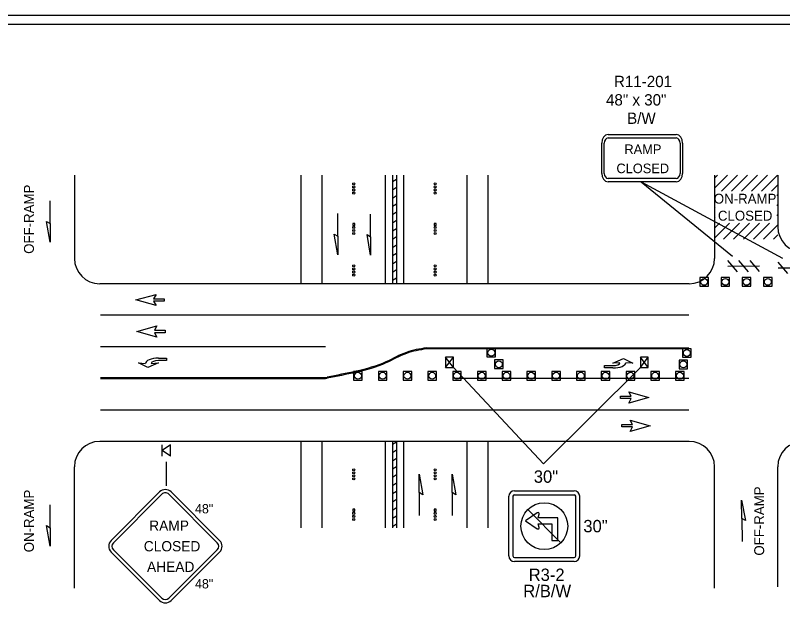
# Model space of a CAD drawing. Extents: x 99988 to 100172, y 99995 to 100047.
# Drawn here: x 100006.52 to 100011.94, y 100006.27 to 100010.44 of the extents above; entities that cross this region are included whole.
import ezdxf

# ---------------------------------------------------------------- set-up
doc = ezdxf.new("R2010")
doc.units = 0
for name, color, linetype in [('Default', 7, 'Continuous'), ('RD_MK_TrafficArrowType1SNew', 7, 'Continuous'), ('RD_MK_TrafficArrowType2LNew', 7, 'Continuous'), ('SH_DE_DetailBody1Text', 7, 'Continuous'), ('SH_GI_PlotLimits', 7, 'Continuous'), ('SH_GI_SheetBorder', 7, 'Continuous'), ('SH_GI_TrafficMvmntArrowRt1Lane', 7, 'Continuous'), ('TR_SN_RegulatorySigns', 7, 'Continuous'), ('TR_SN_WarningSigns', 7, 'Continuous'), ('TR_WZ_BarricadeType3', 7, 'Continuous'), ('TR_WZ_TrafficSafetyCone', 7, 'Continuous'), ('TR_WZ_WorkZoneDetails', 7, 'Continuous')]:
    doc.layers.add(name, color=color, linetype=linetype)

msp = doc.modelspace()

# ---------------------------------------------------------------- linework, layer by layer
at = {"layer": 'Default'}
for p, q in [((100009.5612, 100007.9496), (100009.6156, 100008.0221)), ((100009.6156, 100007.9496), (100009.5612, 100008.0221)), ((100010.9374, 100007.9496), (100010.9917, 100008.0221)), ((100010.9917, 100007.9496), (100010.9374, 100008.0221)), ((100009.5883, 100007.9857), (100009.5883, 100007.9857)), ((100009.5884, 100007.9858), (100009.5884, 100007.9858)), ((100010.9645, 100007.9858), (100010.9645, 100007.9858)), ((100010.9645, 100007.9857), (100010.9645, 100007.9857)), ((100007.6173, 100007.4044), (100007.5595, 100007.3641)), ((100007.5595, 100007.324), (100007.5595, 100007.4044)), ((100007.6173, 100007.324), (100007.6173, 100007.4044)), ((100007.6173, 100007.324), (100007.5595, 100007.3641))]:
    msp.add_line(p, q, dxfattribs=at)
for points in [[(100009.5612, 100007.9496), (100009.6156, 100007.9496), (100009.6156, 100008.0221), (100009.5612, 100008.0221)], [(100010.9374, 100007.9496), (100010.9917, 100007.9496), (100010.9917, 100008.0221), (100010.9374, 100008.0221)]]:
    msp.add_lwpolyline(points, close=True, dxfattribs=at)
at = {"layer": 'RD_MK_TrafficArrowType1SNew'}
for points in [[(100007.5731, 100008.4189), (100007.4981, 100008.4189), (100007.5148, 100008.3876), (100007.3731, 100008.4272), (100007.5148, 100008.4668), (100007.4981, 100008.4355), (100007.5731, 100008.4355)], [(100007.5784, 100008.1959), (100007.5034, 100008.1959), (100007.5201, 100008.1646), (100007.3784, 100008.2042), (100007.5201, 100008.2438), (100007.5034, 100008.2126), (100007.5784, 100008.2126)], [(100010.7971, 100007.7469), (100010.8721, 100007.7469), (100010.8554, 100007.7782), (100010.9971, 100007.7386), (100010.8554, 100007.699), (100010.8721, 100007.7303), (100010.7971, 100007.7303)], [(100010.8058, 100007.5464), (100010.8808, 100007.5464), (100010.8641, 100007.5777), (100011.0058, 100007.5381), (100010.8641, 100007.4985), (100010.8808, 100007.5298), (100010.8058, 100007.5298)]]:
    msp.add_lwpolyline(points, close=True, dxfattribs=at)
at = {"layer": 'RD_MK_TrafficArrowType2LNew'}
for p, q in [((100007.4401, 100007.9785), (100007.4401, 100007.9785)), ((100007.4818, 100007.9785), (100007.4818, 100007.9785)), ((100007.5318, 100008.016), (100007.5318, 100008.016)), ((100007.5318, 100008.016), (100007.5318, 100008.016)), ((100007.5318, 100007.9993), (100007.5318, 100007.9993)), ((100010.7926, 100007.9841), (100010.7926, 100007.9841)), ((100010.8343, 100007.9841), (100010.8343, 100007.9841)), ((100010.7426, 100007.9633), (100010.7426, 100007.9633)), ((100010.7426, 100007.9467), (100010.7426, 100007.9467)), ((100010.7426, 100007.9467), (100010.7426, 100007.9467))]:
    msp.add_line(p, q, dxfattribs=at)
for points in [[(100007.4818, 100007.9785), (100007.5318, 100007.9827), (100007.4568, 100007.9493), (100007.3901, 100007.9827), (100007.4401, 100007.9785)], [(100007.5318, 100008.016), (100007.5901, 100008.016), (100007.5901, 100007.9993), (100007.5318, 100007.9993)], [(100010.7926, 100007.9841), (100010.7426, 100007.98), (100010.8176, 100008.0133), (100010.8843, 100007.98), (100010.8343, 100007.9841)], [(100010.7426, 100007.9467), (100010.6843, 100007.9467), (100010.6843, 100007.9633), (100010.7426, 100007.9633)]]:
    msp.add_lwpolyline(points, dxfattribs=at)
for centre, major_axis, ratio, start_param in [((100007.5318, 100007.9785), (-0.0917, 0), 0.40879, 4.712524), ((100007.5318, 100007.9785), (-0.05, 0), 0.41611, 4.712518), ((100010.7426, 100007.9841), (0.05, 0), 0.41611, 4.712518), ((100010.7426, 100007.9841), (0.0917, 0), 0.40879, 4.712524)]:
    msp.add_ellipse(centre, major_axis=major_axis, ratio=ratio, start_param=start_param, end_param=6.283185, dxfattribs=at)
at = {"layer": 'SH_GI_PlotLimits'}
msp.add_lwpolyline([(99999.3125, 99999.9375), (100015.8125, 99999.9375), (100015.8125, 100010.4375), (99999.3125, 100010.4375)], close=True, dxfattribs=at)
at = {"layer": 'SH_GI_SheetBorder'}
msp.add_line((100000, 100010.375), (100015.75, 100010.375), dxfattribs=at)
at = {"layer": 'SH_GI_TrafficMvmntArrowRt1Lane'}
for p, q in [((100006.7678, 100008.9661), (100006.7678, 100009.1268)), ((100008.7984, 100008.8766), (100008.7984, 100009.0373)), ((100009.0314, 100008.8735), (100009.0314, 100009.0343)), ((100009.3737, 100007.0664), (100009.3737, 100006.9057)), ((100009.6068, 100007.0664), (100009.6068, 100006.9057)), ((100006.7678, 100006.8186), (100006.7679, 100006.9793)), ((100011.6536, 100006.8828), (100011.6557, 100006.722))]:
    msp.add_line(p, q, dxfattribs=at)
for points in [[(100006.7678, 100008.8351), (100006.742, 100008.981), (100006.7678, 100008.9661)], [(100008.7984, 100008.7456), (100008.7726, 100008.8915), (100008.7984, 100008.8766)], [(100009.0314, 100008.7425), (100009.0057, 100008.8884), (100009.0314, 100008.8735)], [(100009.3737, 100007.1975), (100009.3994, 100007.0516), (100009.3737, 100007.0664)], [(100009.6068, 100007.1975), (100009.6325, 100007.0516), (100009.6068, 100007.0664)], [(100011.6518, 100007.0138), (100011.6795, 100006.8683), (100011.6536, 100006.8828)], [(100006.7678, 100006.6875), (100006.7421, 100006.8334), (100006.7678, 100006.8186)]]:
    msp.add_lwpolyline(points, close=True, dxfattribs=at)
at = {"layer": 'TR_SN_RegulatorySigns'}
for p, q in [((100010.0473, 100007.0796), (100010.469, 100007.0796)), ((100010.0473, 100007.0516), (100010.469, 100007.0516)), ((100010.0081, 100006.6187), (100010.0081, 100007.0405)), ((100010.0361, 100007.0405), (100010.0361, 100006.6187)), ((100010.4801, 100006.6187), (100010.4801, 100007.0405)), ((100010.5081, 100007.0405), (100010.5081, 100006.6187)), ((100010.1412, 100006.9465), (100010.3751, 100006.7127)), ((100010.2087, 100006.9243), (100010.1261, 100006.8677)), ((100010.2087, 100006.9243), (100010.2087, 100006.9243)), ((100010.2139, 100006.8893), (100010.2218, 100006.9146)), ((100010.3538, 100006.8892), (100010.2139, 100006.8892)), ((100010.3538, 100006.7288), (100010.3538, 100006.8892)), ((100010.1261, 100006.8677), (100010.2087, 100006.8111)), ((100010.2139, 100006.8462), (100010.3108, 100006.8462)), ((100010.2218, 100006.8208), (100010.2139, 100006.8461)), ((100010.3108, 100006.8462), (100010.3108, 100006.7288)), ((100010.3108, 100006.7288), (100010.3538, 100006.7288)), ((100010.0473, 100006.6076), (100010.469, 100006.6076)), ((100010.469, 100006.5796), (100010.0473, 100006.5796))]:
    msp.add_line(p, q, dxfattribs=at)
for points in [[(100010.7086, 100009.5951), (100011.1908, 100009.5951)], [(100010.7086, 100009.5713), (100011.1908, 100009.5713)], [(100010.6639, 100009.3213), (100010.6639, 100009.5356)], [(100010.6818, 100009.3213), (100010.6818, 100009.5356)], [(100011.2176, 100009.5356), (100011.2176, 100009.3213)], [(100011.2354, 100009.5356), (100011.2354, 100009.3213)], [(100011.1908, 100009.2856), (100010.7086, 100009.2856)], [(100011.1908, 100009.2618), (100010.7086, 100009.2618)]]:
    msp.add_lwpolyline(points, dxfattribs=at)
msp.add_circle((100010.2581, 100006.8296), 0.1654, dxfattribs=at)
for centre, radius, start, end in [((100010.0473, 100007.0405), 0.0392, 90, 180), ((100010.0473, 100007.0405), 0.0111, 90, 180), ((100010.469, 100007.0405), 0.0392, 0, 90), ((100010.469, 100007.0405), 0.0111, 0, 90), ((100010.0473, 100006.6188), 0.0392, 180, 270), ((100010.0473, 100006.6188), 0.0111, 180, 270), ((100010.469, 100006.6188), 0.0111, 270, 0), ((100010.469, 100006.6188), 0.0392, 270, 0)]:
    msp.add_arc(centre, radius, start, end, dxfattribs=at)
for centre, major_axis, ratio, start_param, end_param in [((100010.7086, 100009.5356), (0, -0.0595), 0.75, 3.141593, 4.712389), ((100011.1908, 100009.5356), (0, 0.0595), 0.75, 4.712389, 6.283185), ((100010.7086, 100009.5356), (0, -0.0357), 0.75, 3.141593, 4.712389), ((100011.1908, 100009.5356), (0, 0.0357), 0.75, 4.712389, 6.283185), ((100010.7086, 100009.3213), (0, -0.0595), 0.75, 4.712389, 6.283185), ((100010.7086, 100009.3213), (0, -0.0357), 0.75, 4.712389, 6.283185), ((100011.1908, 100009.3213), (0, 0.0357), 0.75, 3.141593, 4.712389), ((100011.1908, 100009.3213), (0, 0.0595), 0.75, 3.141593, 4.712389), ((100010.2136, 100006.9172), (0.00326, 0.00797), 0.999219, 4.797876, 7.277037), ((100010.2136, 100006.8182), (0.00326, 0.00797), 0.999219, 2.929663, 5.403892)]:
    msp.add_ellipse(centre, major_axis=major_axis, ratio=ratio, start_param=start_param, end_param=end_param, dxfattribs=at)
at = {"layer": 'TR_SN_WarningSigns'}
for p, q in [((100007.1974, 100006.7284), (100007.5401, 100007.0711)), ((100007.2137, 100006.7121), (100007.5564, 100007.0547)), ((100007.6053, 100007.0547), (100007.948, 100006.7121)), ((100007.6216, 100007.0711), (100007.9643, 100006.7284)), ((100007.5401, 100006.3041), (100007.1974, 100006.6468)), ((100007.5564, 100006.3204), (100007.2137, 100006.6631)), ((100007.948, 100006.6631), (100007.6053, 100006.3204)), ((100007.9643, 100006.6468), (100007.6216, 100006.3041))]:
    msp.add_line(p, q, dxfattribs=at)
for centre, radius, start, end in [((100007.5809, 100007.0303), 0.0577, 44.9963, 134.9997), ((100007.5809, 100007.0303), 0.0346, 44.9963, 134.9997), ((100007.2382, 100006.6876), 0.0577, 134.9966, 224.9936), ((100007.9235, 100006.6876), 0.0577, 314.9994, 44.9948), ((100007.2382, 100006.6876), 0.0346, 134.9966, 224.9936), ((100007.9235, 100006.6876), 0.0346, 314.9994, 44.9948), ((100007.5808, 100006.3449), 0.0577, 225, 314.9996), ((100007.5808, 100006.3449), 0.0346, 225, 314.9996)]:
    msp.add_arc(centre, radius, start, end, dxfattribs=at)
at = {"layer": 'TR_WZ_BarricadeType3'}
for p, q in [((100011.6222, 100008.6262), (100011.5547, 100008.7049)), ((100011.7007, 100008.6269), (100011.6332, 100008.7056)), ((100011.7792, 100008.6276), (100011.7117, 100008.7063)), ((100011.9777, 100008.6146), (100011.91, 100008.6932)), ((100011.555, 100008.6653), (100011.7788, 100008.6672)), ((100011.9104, 100008.6535), (100012.1342, 100008.6558))]:
    msp.add_line(p, q, dxfattribs=at)
at = {"layer": 'TR_WZ_TrafficSafetyCone'}
for points in [[(100011.4178, 100008.5246), (100011.4178, 100008.5853), (100011.3571, 100008.5853), (100011.3571, 100008.5246)], [(100011.5678, 100008.5246), (100011.5678, 100008.5853), (100011.5071, 100008.5853), (100011.5071, 100008.5246)], [(100011.7178, 100008.5246), (100011.7178, 100008.5853), (100011.6571, 100008.5853), (100011.6571, 100008.5246)], [(100011.8678, 100008.5246), (100011.8678, 100008.5853), (100011.8071, 100008.5853), (100011.8071, 100008.5246)], [(100009.8529, 100008.0243), (100009.9137, 100008.0243), (100009.9137, 100008.085), (100009.8529, 100008.085)], [(100011.2956, 100008.0223), (100011.2956, 100008.083), (100011.2349, 100008.083), (100011.2349, 100008.0223)], [(100009.9069, 100007.9428), (100009.9677, 100007.9428), (100009.9677, 100008.0035), (100009.9069, 100008.0035)], [(100011.2711, 100007.9418), (100011.2711, 100008.0025), (100011.2105, 100008.0025), (100011.2105, 100007.9418)], [(100008.911, 100007.8613), (100008.9717, 100007.8613), (100008.9717, 100007.922), (100008.911, 100007.922)], [(100009.086, 100007.8613), (100009.1467, 100007.8613), (100009.1467, 100007.922), (100009.086, 100007.922)], [(100009.261, 100007.8613), (100009.3217, 100007.8613), (100009.3217, 100007.922), (100009.261, 100007.922)], [(100009.436, 100007.8613), (100009.4967, 100007.8613), (100009.4967, 100007.922), (100009.436, 100007.922)], [(100009.6717, 100007.8613), (100009.6717, 100007.922), (100009.611, 100007.922), (100009.611, 100007.8613)], [(100009.786, 100007.8613), (100009.8467, 100007.8613), (100009.8467, 100007.922), (100009.786, 100007.922)], [(100009.961, 100007.8613), (100010.0217, 100007.8613), (100010.0217, 100007.922), (100009.961, 100007.922)], [(100010.1967, 100007.8613), (100010.1967, 100007.922), (100010.136, 100007.922), (100010.136, 100007.8613)], [(100010.311, 100007.8613), (100010.3717, 100007.8613), (100010.3717, 100007.922), (100010.311, 100007.922)], [(100010.5467, 100007.8613), (100010.5467, 100007.922), (100010.486, 100007.922), (100010.486, 100007.8613)], [(100010.7217, 100007.8613), (100010.7217, 100007.922), (100010.661, 100007.922), (100010.661, 100007.8613)], [(100010.8967, 100007.8613), (100010.8967, 100007.922), (100010.836, 100007.922), (100010.836, 100007.8613)], [(100011.0717, 100007.8613), (100011.0717, 100007.922), (100011.011, 100007.922), (100011.011, 100007.8613)], [(100011.2467, 100007.8613), (100011.2467, 100007.922), (100011.186, 100007.922), (100011.186, 100007.8613)]]:
    msp.add_lwpolyline(points, close=True, dxfattribs=at)
for centre in [(100011.3875, 100008.5549), (100011.5375, 100008.5549), (100011.6875, 100008.5549), (100011.8375, 100008.5549), (100009.8833, 100008.0547), (100011.2653, 100008.0526), (100009.9373, 100007.9732), (100011.2408, 100007.9721), (100008.9413, 100007.8916), (100009.1163, 100007.8916), (100009.2913, 100007.8916), (100009.4663, 100007.8916), (100009.6413, 100007.8916), (100009.8163, 100007.8916), (100009.9913, 100007.8916), (100010.1663, 100007.8916), (100010.3413, 100007.8916), (100010.5163, 100007.8916), (100010.6913, 100007.8916), (100010.8663, 100007.8916), (100011.0413, 100007.8916), (100011.2163, 100007.8916)]:
    msp.add_circle(centre, 0.0244, dxfattribs=at)
at = {"layer": 'TR_WZ_WorkZoneDetails'}
for p, q in [((100006.9383, 100009.3085), (100006.9383, 100008.7205)), ((100008.5382, 100009.3085), (100008.5382, 100008.5417)), ((100008.6872, 100009.3085), (100008.6872, 100008.5417)), ((100009.135, 100009.3085), (100009.135, 100008.5417)), ((100009.1847, 100009.3085), (100009.1847, 100008.5417)), ((100009.1847, 100009.2631), (100009.2145, 100009.2811)), ((100009.2145, 100009.3085), (100009.2145, 100008.5417)), ((100009.2641, 100009.3085), (100009.2641, 100008.5417)), ((100009.7107, 100009.3085), (100009.7107, 100008.5417)), ((100009.8598, 100009.3085), (100009.8598, 100008.5417)), ((100011.4609, 100009.3085), (100011.4609, 100008.7205)), ((100011.4609, 100009.2878), (100011.4816, 100009.3085)), ((100011.4609, 100009.2171), (100011.5523, 100009.3085)), ((100011.5099, 100009.1954), (100011.623, 100009.3085)), ((100011.5807, 100009.1954), (100011.6937, 100009.3085)), ((100011.6514, 100009.1954), (100011.7644, 100009.3085)), ((100011.7221, 100009.1954), (100011.8352, 100009.3085)), ((100011.7928, 100009.1954), (100011.9059, 100009.3085)), ((100011.9079, 100009.3085), (100011.9079, 100008.944)), ((100009.1847, 100009.205), (100009.2145, 100009.223)), ((100010.9435, 100009.2624), (100011.5885, 100008.7361)), ((100010.9435, 100009.2624), (100011.9417, 100008.7232)), ((100011.8635, 100009.1954), (100011.9079, 100009.2399)), ((100009.1847, 100009.147), (100009.2145, 100009.165)), ((100011.9026, 100009.1638), (100011.9079, 100009.1692)), ((100009.1847, 100009.0889), (100009.2145, 100009.1069)), ((100011.4609, 100009.1464), (100011.466, 100009.1516)), ((100011.4609, 100009.0757), (100011.466, 100009.0808)), ((100011.9026, 100009.0931), (100011.9079, 100009.0984)), ((100009.1847, 100009.0308), (100009.2145, 100009.0489)), ((100011.4609, 100009.005), (100011.466, 100009.0101)), ((100011.9026, 100009.0224), (100011.9079, 100009.0277)), ((100009.1847, 100008.9728), (100009.2145, 100008.9908)), ((100011.4609, 100008.9342), (100011.4958, 100008.9692)), ((100011.4609, 100008.8635), (100011.5665, 100008.9692)), ((100011.5242, 100008.8561), (100011.6372, 100008.9692)), ((100011.5949, 100008.8561), (100011.708, 100008.9692)), ((100011.6656, 100008.8561), (100011.7787, 100008.9692)), ((100011.7363, 100008.8561), (100011.8494, 100008.9692)), ((100011.807, 100008.8561), (100011.9079, 100008.957)), ((100009.1847, 100008.9147), (100009.2145, 100008.9327)), ((100009.1847, 100008.8567), (100009.2145, 100008.8747)), ((100011.8777, 100008.8561), (100011.9079, 100008.8863)), ((100009.1847, 100008.7986), (100009.2145, 100008.8166)), ((100009.1847, 100008.7406), (100009.2145, 100008.7586)), ((100009.1847, 100008.6825), (100009.2145, 100008.7005)), ((100009.1847, 100008.6244), (100009.2145, 100008.6424)), ((100009.1847, 100008.5664), (100009.2145, 100008.5844)), ((100011.2821, 100008.5417), (100007.117, 100008.5417)), ((100011.2794, 100008.32), (100007.123, 100008.32)), ((100008.7125, 100008.0965), (100007.123, 100008.0965)), ((100009.4259, 100008.089), (100011.2787, 100008.089)), ((100011.2787, 100008.0815), (100009.426, 100008.0815)), ((100009.6156, 100007.9496), (100010.2536, 100007.2701)), ((100010.9374, 100007.9496), (100010.2536, 100007.2701)), ((100007.123, 100007.8804), (100008.7115, 100007.8804)), ((100007.123, 100007.8729), (100008.7125, 100007.8729)), ((100007.4179, 100007.872), (100007.418, 100007.8721)), ((100007.8318, 100007.8804), (100007.8764, 100007.8804)), ((100008.7115, 100007.8804), (100008.7235, 100007.8823)), ((100008.7125, 100007.8729), (100008.7236, 100007.8749)), ((100011.2787, 100007.8729), (100009.6229, 100007.8729)), ((100011.2787, 100007.6494), (100007.123, 100007.6494)), ((100011.2821, 100007.4277), (100007.117, 100007.4277)), ((100008.5382, 100007.4277), (100008.5382, 100006.8187)), ((100008.6872, 100007.4277), (100008.6872, 100006.8187)), ((100009.135, 100007.4277), (100009.135, 100006.8187)), ((100009.1847, 100007.4277), (100009.1847, 100006.8187)), ((100009.2145, 100007.4277), (100009.2145, 100006.8187)), ((100009.2641, 100007.4277), (100009.2641, 100006.8187)), ((100009.7107, 100007.4277), (100009.7107, 100006.8187)), ((100009.8598, 100007.4277), (100009.8598, 100006.8187)), ((100009.1847, 100007.4074), (100009.2145, 100007.4255)), ((100009.1847, 100007.3494), (100009.2145, 100007.3674)), ((100007.5869, 100007.284), (100007.5869, 100007.114)), ((100009.1847, 100007.2913), (100009.2145, 100007.3094)), ((100006.9383, 100006.3918), (100006.9383, 100007.2489)), ((100009.1847, 100007.2333), (100009.2145, 100007.2513)), ((100011.4609, 100006.3918), (100011.4609, 100007.2489)), ((100011.9079, 100006.4019), (100011.9079, 100007.2489)), ((100009.1847, 100007.1752), (100009.2145, 100007.1933)), ((100009.1847, 100007.1172), (100009.2145, 100007.1352)), ((100009.1847, 100007.0591), (100009.2145, 100007.0771)), ((100009.1847, 100007.001), (100009.2145, 100007.019)), ((100009.1847, 100006.943), (100009.2145, 100006.961)), ((100009.1847, 100006.8849), (100009.2145, 100006.9029)), ((100009.1847, 100006.8269), (100009.2145, 100006.8449))]:
    msp.add_line(p, q, dxfattribs=at)
for points in [[(100008.9185, 100008.9537), (100008.9185, 100008.9677), (100008.9044, 100008.9677), (100008.9044, 100008.9537), (100008.9185, 100008.9537)], [(100009.4947, 100008.9537), (100009.4947, 100008.9677), (100009.4806, 100008.9677), (100009.4806, 100008.9537), (100009.4947, 100008.9537)], [(100008.9185, 100006.9344), (100008.9185, 100006.9485), (100008.9044, 100006.9485), (100008.9044, 100006.9344), (100008.9185, 100006.9344)], [(100009.4947, 100006.9344), (100009.4947, 100006.9485), (100009.4806, 100006.9485), (100009.4806, 100006.9344), (100009.4947, 100006.9344)]]:
    msp.add_lwpolyline(points, dxfattribs=at)
for centre in [(100008.9115, 100009.2468), (100008.9115, 100009.2253), (100009.4877, 100009.2468), (100009.4877, 100009.2253), (100008.9115, 100009.2039), (100008.9115, 100009.1824), (100009.4877, 100009.2039), (100009.4877, 100009.1824), (100008.9115, 100008.9393), (100009.4877, 100008.9393), (100008.9115, 100008.9178), (100008.9115, 100008.8963), (100009.4877, 100008.9178), (100009.4877, 100008.8963), (100008.9115, 100008.6675), (100009.4877, 100008.6675), (100008.9115, 100008.6461), (100008.9115, 100008.6246), (100009.4877, 100008.6461), (100009.4877, 100008.6246), (100008.9115, 100008.6031), (100009.4877, 100008.6031), (100008.9115, 100007.2275), (100008.9115, 100007.206), (100009.4877, 100007.2275), (100009.4877, 100007.206), (100008.9115, 100007.1846), (100008.9115, 100007.1631), (100009.4877, 100007.1846), (100009.4877, 100007.1631), (100008.9115, 100006.92), (100008.9115, 100006.8985), (100008.9115, 100006.8771), (100009.4877, 100006.92), (100009.4877, 100006.8985), (100009.4877, 100006.8771)]:
    msp.add_circle(centre, 0.00715, dxfattribs=at)
for centre, start, end in [((100012.0867, 100008.944), 180, 270), ((100007.117, 100008.7205), 180, 270), ((100011.2821, 100008.7205), 270, 0), ((100007.117, 100007.2489), 90, 180), ((100011.2821, 100007.2489), 0, 90), ((100012.0867, 100007.2489), 90, 180)]:
    msp.add_arc(centre, 0.1788, start, end, dxfattribs=at)
for points in [[(100009.4259, 100008.089), (100009.2839, 100008.0571), (100009.1394, 100007.9896), (100008.9289, 100007.9235), (100008.7235, 100007.8823)], [(100009.426, 100008.0815), (100009.2839, 100008.0496), (100009.1395, 100007.9821), (100008.9289, 100007.9161), (100008.7236, 100007.8749)]]:
    msp.add_spline(points, degree=3, dxfattribs=at)

# ---------------------------------------------------------------- texts
at = {"layer": 'SH_DE_DetailBody1Text'}
for s, height, p in [('R11-201', 0.08, (100010.7504, 100009.9307)), ('48" x 30"', 0.08, (100010.6942, 100009.8007)), ('B/W', 0.08, (100010.8433, 100009.6707)), ('ON-RAMP', 0.07, (100011.4559, 100009.1073)), ('CLOSED', 0.07, (100011.4849, 100008.9873))]:
    msp.add_text(s, height=height, dxfattribs=at).set_placement(p)
for s, p in [('OFF-RAMP', (100006.6521, 100008.7529)), ('OFF-RAMP', (100011.8115, 100006.6211)), ('ON-RAMP', (100006.6521, 100006.6448))]:
    msp.add_text(s, height=0.07, rotation=90, dxfattribs=at).set_placement(p)
at = {"layer": 'TR_SN_RegulatorySigns'}
for s, height, p in [('RAMP', 0.06769, (100010.8241, 100009.4581)), ('CLOSED', 0.06769, (100010.7679, 100009.3227)), ('30"', 0.0875, (100010.1841, 100007.1359)), ('30"', 0.0875, (100010.5341, 100006.7859)), ('R3-2', 0.0875, (100010.148, 100006.4422)), ('R/B/W', 0.0875, (100010.1095, 100006.3276))]:
    msp.add_text(s, height=height, dxfattribs=at).set_placement(p)
at = {"layer": 'TR_SN_WarningSigns'}
for s, height, p in [('48"', 0.06563, (100007.7905, 100006.9199)), ('RAMP', 0.07268, (100007.4668, 100006.7966)), ('CLOSED', 0.07268, (100007.4284, 100006.6513)), ('AHEAD', 0.07268, (100007.4512, 100006.5059)), ('48"', 0.06563, (100007.7905, 100006.3896))]:
    msp.add_text(s, height=height, dxfattribs=at).set_placement(p)

doc.saveas('drawing.dxf')
